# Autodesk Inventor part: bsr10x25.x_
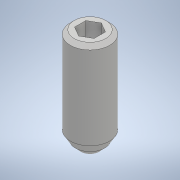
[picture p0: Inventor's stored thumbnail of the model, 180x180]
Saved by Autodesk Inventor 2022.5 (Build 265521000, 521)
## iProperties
Created: 2020-01
Part Number: bsr10x25.x_
Material: 一般
Document SubType Name: Modeling
Designer: ImaoCorp
Density: 1 g/cm^3
Appearance: 既定
Sending System: SOLIDWORKS 2018-2018316
MC: AMD64
MC_MODEL: Intel64 Family 6 Model 60 Stepping 3, GenuineIntel
OS: Windows_NT
FRU: Parasolid Version 30.0, build 310,  6- 8-2018
FORMAT: text
GUISE: transmit
KEY: bsr10x25
FILE: bsr10x25.x_t
DATE: Thu Jan 23 16:48:07 2020
Author: ImaoCorp
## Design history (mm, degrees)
feature "Base1"
node "ソリッド1"
